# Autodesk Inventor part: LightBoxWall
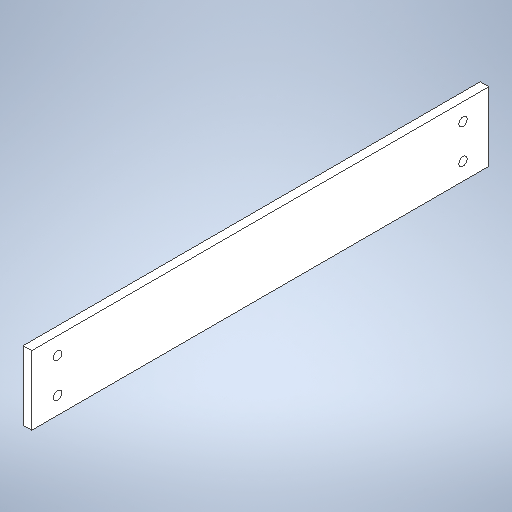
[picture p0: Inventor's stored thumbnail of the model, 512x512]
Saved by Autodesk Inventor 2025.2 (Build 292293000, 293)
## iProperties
Created: 2025-09
Part Number: LightBoxWall
Material: Generic
Document SubType Name: Modeling
Designer: tyler
Density: 1 g/cm^3
Appearance: Default
Author: tyler
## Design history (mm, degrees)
sketch "Sketch1"
  geometry: L1 (-25.4, 168.529)-(25.4, 168.529); L2 (25.4, 168.529)-(25.4, -168.529); L3 (25.4, -168.529)-(-25.4, -168.529); L4 (-25.4, -168.529)-(-25.4, 168.529); L5 (-25.4, 168.529)-(25.4, -168.529); L6 (25.4, 168.529)-(-25.4, -168.529); 1 further point
  constraints: 12 end point, 2 midpoint, 2 parallel, 1 horizontal, 1 perpendicular
  dimensions: "d0" = 50.8 distance of L2.end L3.end; "d1" = 337.058 distance of L1.end L2.end
extrude "Extrusion1" new body sketch "Sketch1" distance "d2" = 6.35; taper "d3" = 0 deg
sketch "Sketch2"
  geometry: L1 (168.529, 25.4)-(-168.529, 25.4) reference; L2 (-168.529, 25.4)-(-149.479, 25.4); L3 (-149.479, 25.4)-(-149.479, 12.7); L4 (-168.529, 25.4)-(-168.529, -25.4) reference; L5 (-168.529, -25.4)-(-149.479, -25.4); L6 (-168.529, -25.4)-(168.529, -25.4) reference; L7 (-149.479, -25.4)-(-149.479, -12.7); L8 (0, 25.4)-(0, 9.525); C1 r 3.175 at (-149.479, 12.7); C2 r 3.175 at (-149.479, -12.7); C3 r 3.175 at (149.479, 12.7); C4 r 3.175 at (149.479, -12.7); 1 further point
  constraints: 10 end point, 4 centre point, 2 coincident, 2 point on line, 2 symmetric about line, 2 vertical, 1 midpoint, 1 perpendicular, 2 other
  dimensions: "d4" = 19.05 distance of L1.end L2.end; "d6" = 12.7 distance of L2.end L3.end; "d7" = 6.35 diameter of C1; "d8" = 19.05 distance of L4.end L5.end; "d9" = 12.7 distance of L5.end L7.end; "d10" = 6.35 diameter of C2
extrude "Extrusion2" cut sketch "Sketch2" distance "d11" = 6.35; taper "d12" = 0 deg
body "Solid1"
